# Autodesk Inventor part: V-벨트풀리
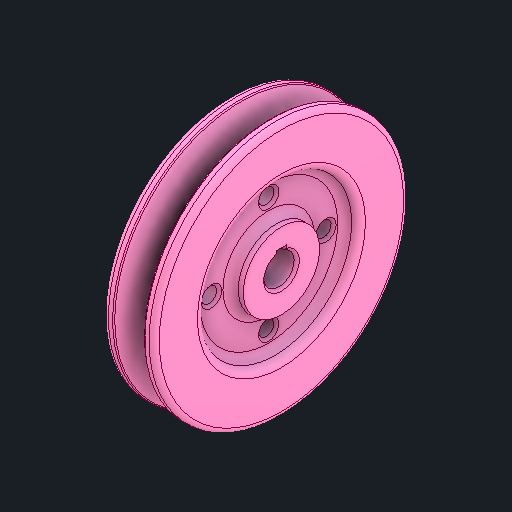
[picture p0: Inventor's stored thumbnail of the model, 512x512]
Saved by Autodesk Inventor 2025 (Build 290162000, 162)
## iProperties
Created: 2025-08
Part Number: V-벨트풀리
Material: 강철, 연강
Document SubType Name: Modeling
Designer: infra10
Density: 7.86 g/cm^3
Appearance: 기본값
Author: jhkim
Sending System: Autodesk Inventor 2026
Preprocessor: ST-DEVELOPER v20.1
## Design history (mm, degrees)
feature "솔리드1"
node "솔리드2"
